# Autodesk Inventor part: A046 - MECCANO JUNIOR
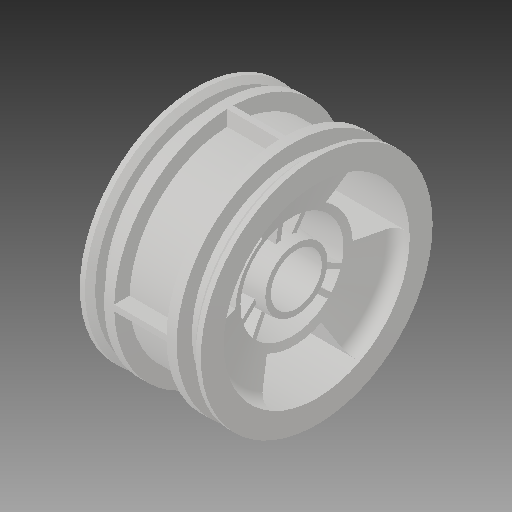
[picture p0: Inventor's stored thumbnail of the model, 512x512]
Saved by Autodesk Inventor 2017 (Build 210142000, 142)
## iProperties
Created: 2016-10
Part Number: A046 - MECCANO JUNIOR
Material: solidworks materials|PVC rigide
Document SubType Name: Modeling
Designer: ficho
Density: 1.3 g/cm^3
Appearance: 192,192,192
Mass: 15.5589 g
Surface Area: 152.048 cm^2
Volume: 11.9684 cm^3
Sending System: SolidWorks 2013
Last Author: lucie-nico
Last Saved: 2016-10-25
Author: ficho
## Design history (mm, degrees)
feature "Boss.-Extru.5"
node "Solide1"
